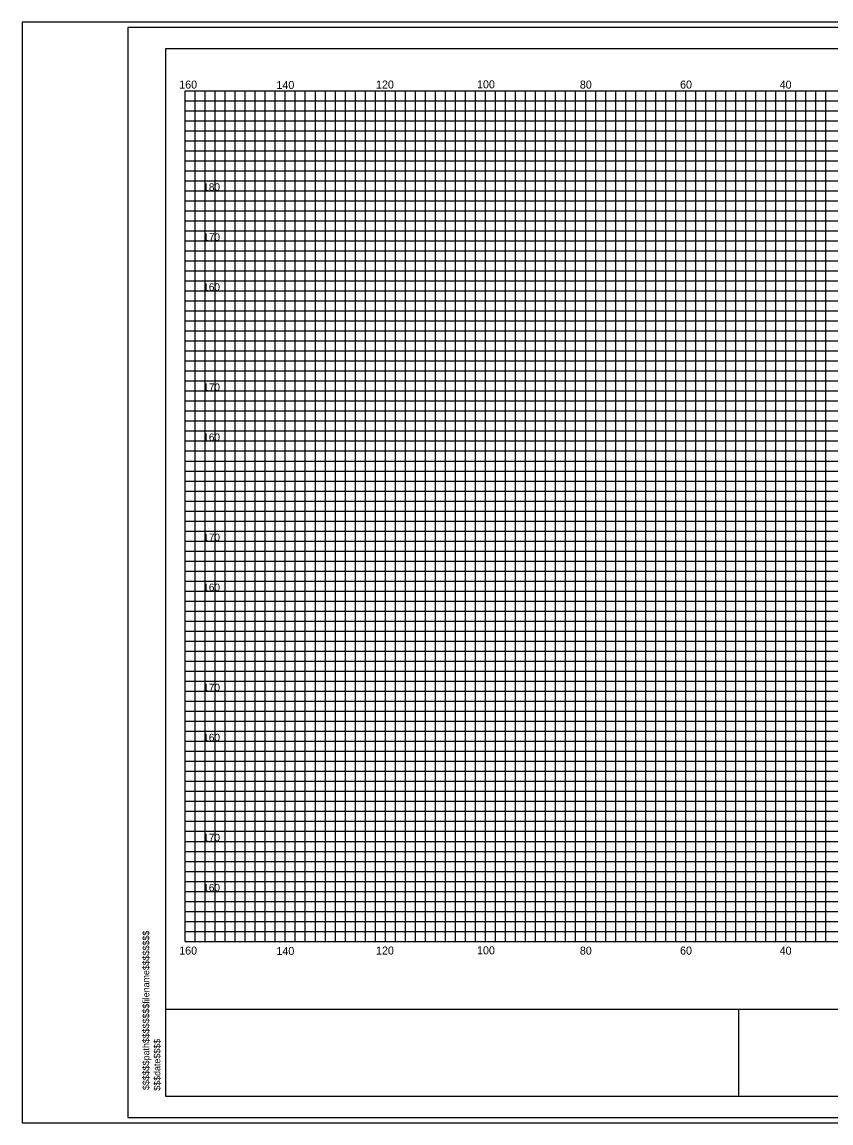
# Model space of a CAD drawing. Extents: x 967 to 1326, y 964 to 2864.
# Drawn here: x 967.4 to 1129, y 1243.7 to 1463.7 of the extents above; entities that cross this region are included whole.
import ezdxf

# ---------------------------------------------------------------- set-up
doc = ezdxf.new("R2010")
doc.units = 0
for name, color, linetype in [('Default', 7, 'Continuous'), ('RD_EX_RW', 7, 'Continuous'), ('RD_PD_Final_TX', 7, 'Continuous'), ('RD_SHT_ShtClip', 7, 'Continuous'), ('RD_XS_TX_Elev_PR', 7, 'Continuous'), ('RD_XS_TX_Slope', 7, 'Continuous')]:
    doc.layers.add(name, color=color, linetype=linetype)

msp = doc.modelspace()

# ---------------------------------------------------------------- linework, layer by layer
at = {"layer": 'RD_EX_RW'}
for p, q in [((1000, 1450), (1320, 1450)), ((1000, 1280), (1000, 1450)), ((1010, 1280), (1010, 1450)), ((1020, 1280), (1020, 1450)), ((1030, 1280), (1030, 1450)), ((1040, 1280), (1040, 1450)), ((1050, 1280), (1050, 1450)), ((1060, 1280), (1060, 1450)), ((1070, 1280), (1070, 1450)), ((1080, 1280), (1080, 1450)), ((1090, 1280), (1090, 1450)), ((1100, 1280), (1100, 1450)), ((1110, 1280), (1110, 1450)), ((1120, 1280), (1120, 1450)), ((1000, 1440), (1320, 1440)), ((1000, 1430), (1320, 1430)), ((1000, 1420), (1320, 1420)), ((1000, 1410), (1320, 1410)), ((1000, 1400), (1320, 1400)), ((1000, 1390), (1320, 1390)), ((1000, 1380), (1320, 1380)), ((1000, 1370), (1320, 1370)), ((1000, 1360), (1320, 1360)), ((1000, 1350), (1320, 1350)), ((1000, 1340), (1320, 1340)), ((1000, 1330), (1320, 1330)), ((1000, 1320), (1320, 1320)), ((1000, 1310), (1320, 1310)), ((1000, 1300), (1320, 1300)), ((1000, 1290), (1320, 1290)), ((1000, 1280), (1320, 1280))]:
    msp.add_line(p, q, dxfattribs=at)
at = {"layer": 'RD_PD_Final_TX'}
for p, q in [((996.11, 1248.98), (996.11, 1458.46)), ((996.11, 1458.46), (1323.89, 1458.46)), ((996.11, 1266.49), (1323.89, 1266.49)), ((1110.59, 1248.98), (1110.59, 1266.56)), ((1323.89, 1248.98), (996.11, 1248.98))]:
    msp.add_line(p, q, dxfattribs=at)
at = {"layer": 'RD_SHT_ShtClip'}
for p, q in [((1002, 1280), (1002, 1450)), ((1004, 1280), (1004, 1450)), ((1006, 1280), (1006, 1450)), ((1008, 1280), (1008, 1450)), ((1012, 1280), (1012, 1450)), ((1014, 1280), (1014, 1450)), ((1016, 1280), (1016, 1450)), ((1018, 1280), (1018, 1450)), ((1022, 1280), (1022, 1450)), ((1024, 1280), (1024, 1450)), ((1026, 1280), (1026, 1450)), ((1028, 1280), (1028, 1450)), ((1032, 1280), (1032, 1450)), ((1034, 1280), (1034, 1450)), ((1036, 1280), (1036, 1450)), ((1038, 1280), (1038, 1450)), ((1042, 1280), (1042, 1450)), ((1044, 1280), (1044, 1450)), ((1046, 1280), (1046, 1450)), ((1048, 1280), (1048, 1450)), ((1052, 1280), (1052, 1450)), ((1054, 1280), (1054, 1450)), ((1056, 1280), (1056, 1450)), ((1058, 1280), (1058, 1450)), ((1062, 1280), (1062, 1450)), ((1064, 1280), (1064, 1450)), ((1066, 1280), (1066, 1450)), ((1068, 1280), (1068, 1450)), ((1072, 1280), (1072, 1450)), ((1074, 1280), (1074, 1450)), ((1076, 1280), (1076, 1450)), ((1078, 1280), (1078, 1450)), ((1082, 1280), (1082, 1450)), ((1084, 1280), (1084, 1450)), ((1086, 1280), (1086, 1450)), ((1088, 1280), (1088, 1450)), ((1092, 1280), (1092, 1450)), ((1094, 1280), (1094, 1450)), ((1096, 1280), (1096, 1450)), ((1098, 1280), (1098, 1450)), ((1102, 1280), (1102, 1450)), ((1104, 1280), (1104, 1450)), ((1106, 1280), (1106, 1450)), ((1108, 1280), (1108, 1450)), ((1112, 1280), (1112, 1450)), ((1114, 1280), (1114, 1450)), ((1116, 1280), (1116, 1450)), ((1118, 1280), (1118, 1450)), ((1122, 1280), (1122, 1450)), ((1124, 1280), (1124, 1450)), ((1126, 1280), (1126, 1450)), ((1128, 1280), (1128, 1450)), ((1000, 1448), (1320, 1448)), ((1000, 1446), (1320, 1446)), ((1000, 1444), (1320, 1444)), ((1000, 1442), (1320, 1442)), ((1000, 1438), (1320, 1438)), ((1000, 1436), (1320, 1436)), ((1000, 1434), (1320, 1434)), ((1000, 1432), (1320, 1432)), ((1000, 1428), (1320, 1428)), ((1000, 1426), (1320, 1426)), ((1000, 1424), (1320, 1424)), ((1000, 1422), (1320, 1422)), ((1000, 1418), (1320, 1418)), ((1000, 1416), (1320, 1416)), ((1000, 1414), (1320, 1414)), ((1000, 1412), (1320, 1412)), ((1000, 1408), (1320, 1408)), ((1000, 1406), (1320, 1406)), ((1000, 1404), (1320, 1404)), ((1000, 1402), (1320, 1402)), ((1000, 1398), (1320, 1398)), ((1000, 1396), (1320, 1396)), ((1000, 1394), (1320, 1394)), ((1000, 1392), (1320, 1392)), ((1000, 1388), (1320, 1388)), ((1000, 1386), (1320, 1386)), ((1000, 1384), (1320, 1384)), ((1000, 1382), (1320, 1382)), ((1000, 1378), (1320, 1378)), ((1000, 1376), (1320, 1376)), ((1000, 1374), (1320, 1374)), ((1000, 1372), (1320, 1372)), ((1000, 1368), (1320, 1368)), ((1000, 1366), (1320, 1366)), ((1000, 1364), (1320, 1364)), ((1000, 1362), (1320, 1362)), ((1000, 1358), (1320, 1358)), ((1000, 1356), (1320, 1356)), ((1000, 1354), (1320, 1354)), ((1000, 1352), (1320, 1352)), ((1000, 1348), (1320, 1348)), ((1000, 1346), (1320, 1346)), ((1000, 1344), (1320, 1344)), ((1000, 1342), (1320, 1342)), ((1000, 1338), (1320, 1338)), ((1000, 1336), (1320, 1336)), ((1000, 1334), (1320, 1334)), ((1000, 1332), (1320, 1332)), ((1000, 1328), (1320, 1328)), ((1000, 1326), (1320, 1326)), ((1000, 1324), (1320, 1324)), ((1000, 1322), (1320, 1322)), ((1000, 1318), (1320, 1318)), ((1000, 1316), (1320, 1316)), ((1000, 1314), (1320, 1314)), ((1000, 1312), (1320, 1312)), ((1000, 1308), (1320, 1308)), ((1000, 1306), (1320, 1306)), ((1000, 1304), (1320, 1304)), ((1000, 1302), (1320, 1302)), ((1000, 1298), (1320, 1298)), ((1000, 1296), (1320, 1296)), ((1000, 1294), (1320, 1294)), ((1000, 1292), (1320, 1292)), ((1000, 1288), (1320, 1288)), ((1000, 1286), (1320, 1286)), ((1000, 1284), (1320, 1284)), ((1000, 1282), (1320, 1282))]:
    msp.add_line(p, q, dxfattribs=at)
at = {"layer": 'RD_XS_TX_Elev_PR'}
for points in [[(967.41, 1243.72), (1326.28, 1243.72), (1326.28, 1463.72), (967.41, 1463.72)], [(988.52, 1244.84), (1326.28, 1244.84), (1326.28, 1462.6), (988.52, 1462.6)]]:
    msp.add_lwpolyline(points, close=True, dxfattribs=at)

# ---------------------------------------------------------------- texts
at = {"layer": 'Default'}
for s, p in [('180', (1003.61, 1430)), ('170', (1003.61, 1420)), ('160', (1003.61, 1410)), ('170', (1003.61, 1390)), ('160', (1003.61, 1380)), ('170', (1003.61, 1360)), ('160', (1003.61, 1350)), ('170', (1003.61, 1330)), ('160', (1003.61, 1320)), ('170', (1003.61, 1300)), ('160', (1003.61, 1290))]:
    msp.add_text(s, height=1.5, dxfattribs=at).set_placement(p)
for s, p in [('$$$$$$path$$$$$$$$filename$$$$$$$$', (992.83, 1250.31)), ('$$$date$$$$', (995.04, 1250.17))]:
    msp.add_text(s, height=1.3258, rotation=90, dxfattribs=at).set_placement(p)
at = {"layer": 'RD_XS_TX_Slope'}
for s, p in [('160', (998.81, 1450.42)), ('120', (1038.12, 1450.43)), ('100', (1058.3, 1450.47)), ('80', (1078.84, 1450.42)), ('60', (1098.86, 1450.42)), ('40', (1118.75, 1450.41)), ('140', (1018.23, 1450.34)), ('160', (998.81, 1277.37)), ('140', (1018.23, 1277.29)), ('120', (1038.12, 1277.38)), ('100', (1058.3, 1277.42)), ('80', (1078.84, 1277.37)), ('60', (1098.86, 1277.37)), ('40', (1118.75, 1277.36))]:
    msp.add_text(s, height=1.6, dxfattribs=at).set_placement(p)

doc.saveas('drawing.dxf')
